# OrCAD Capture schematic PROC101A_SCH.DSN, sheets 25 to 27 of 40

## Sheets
25 35. DEBOUNCE&VOLTAGE-SUPERVISOR: size C; title: DEBOUNCE CIRCUIT & VOLTAGE SUPERVISOR
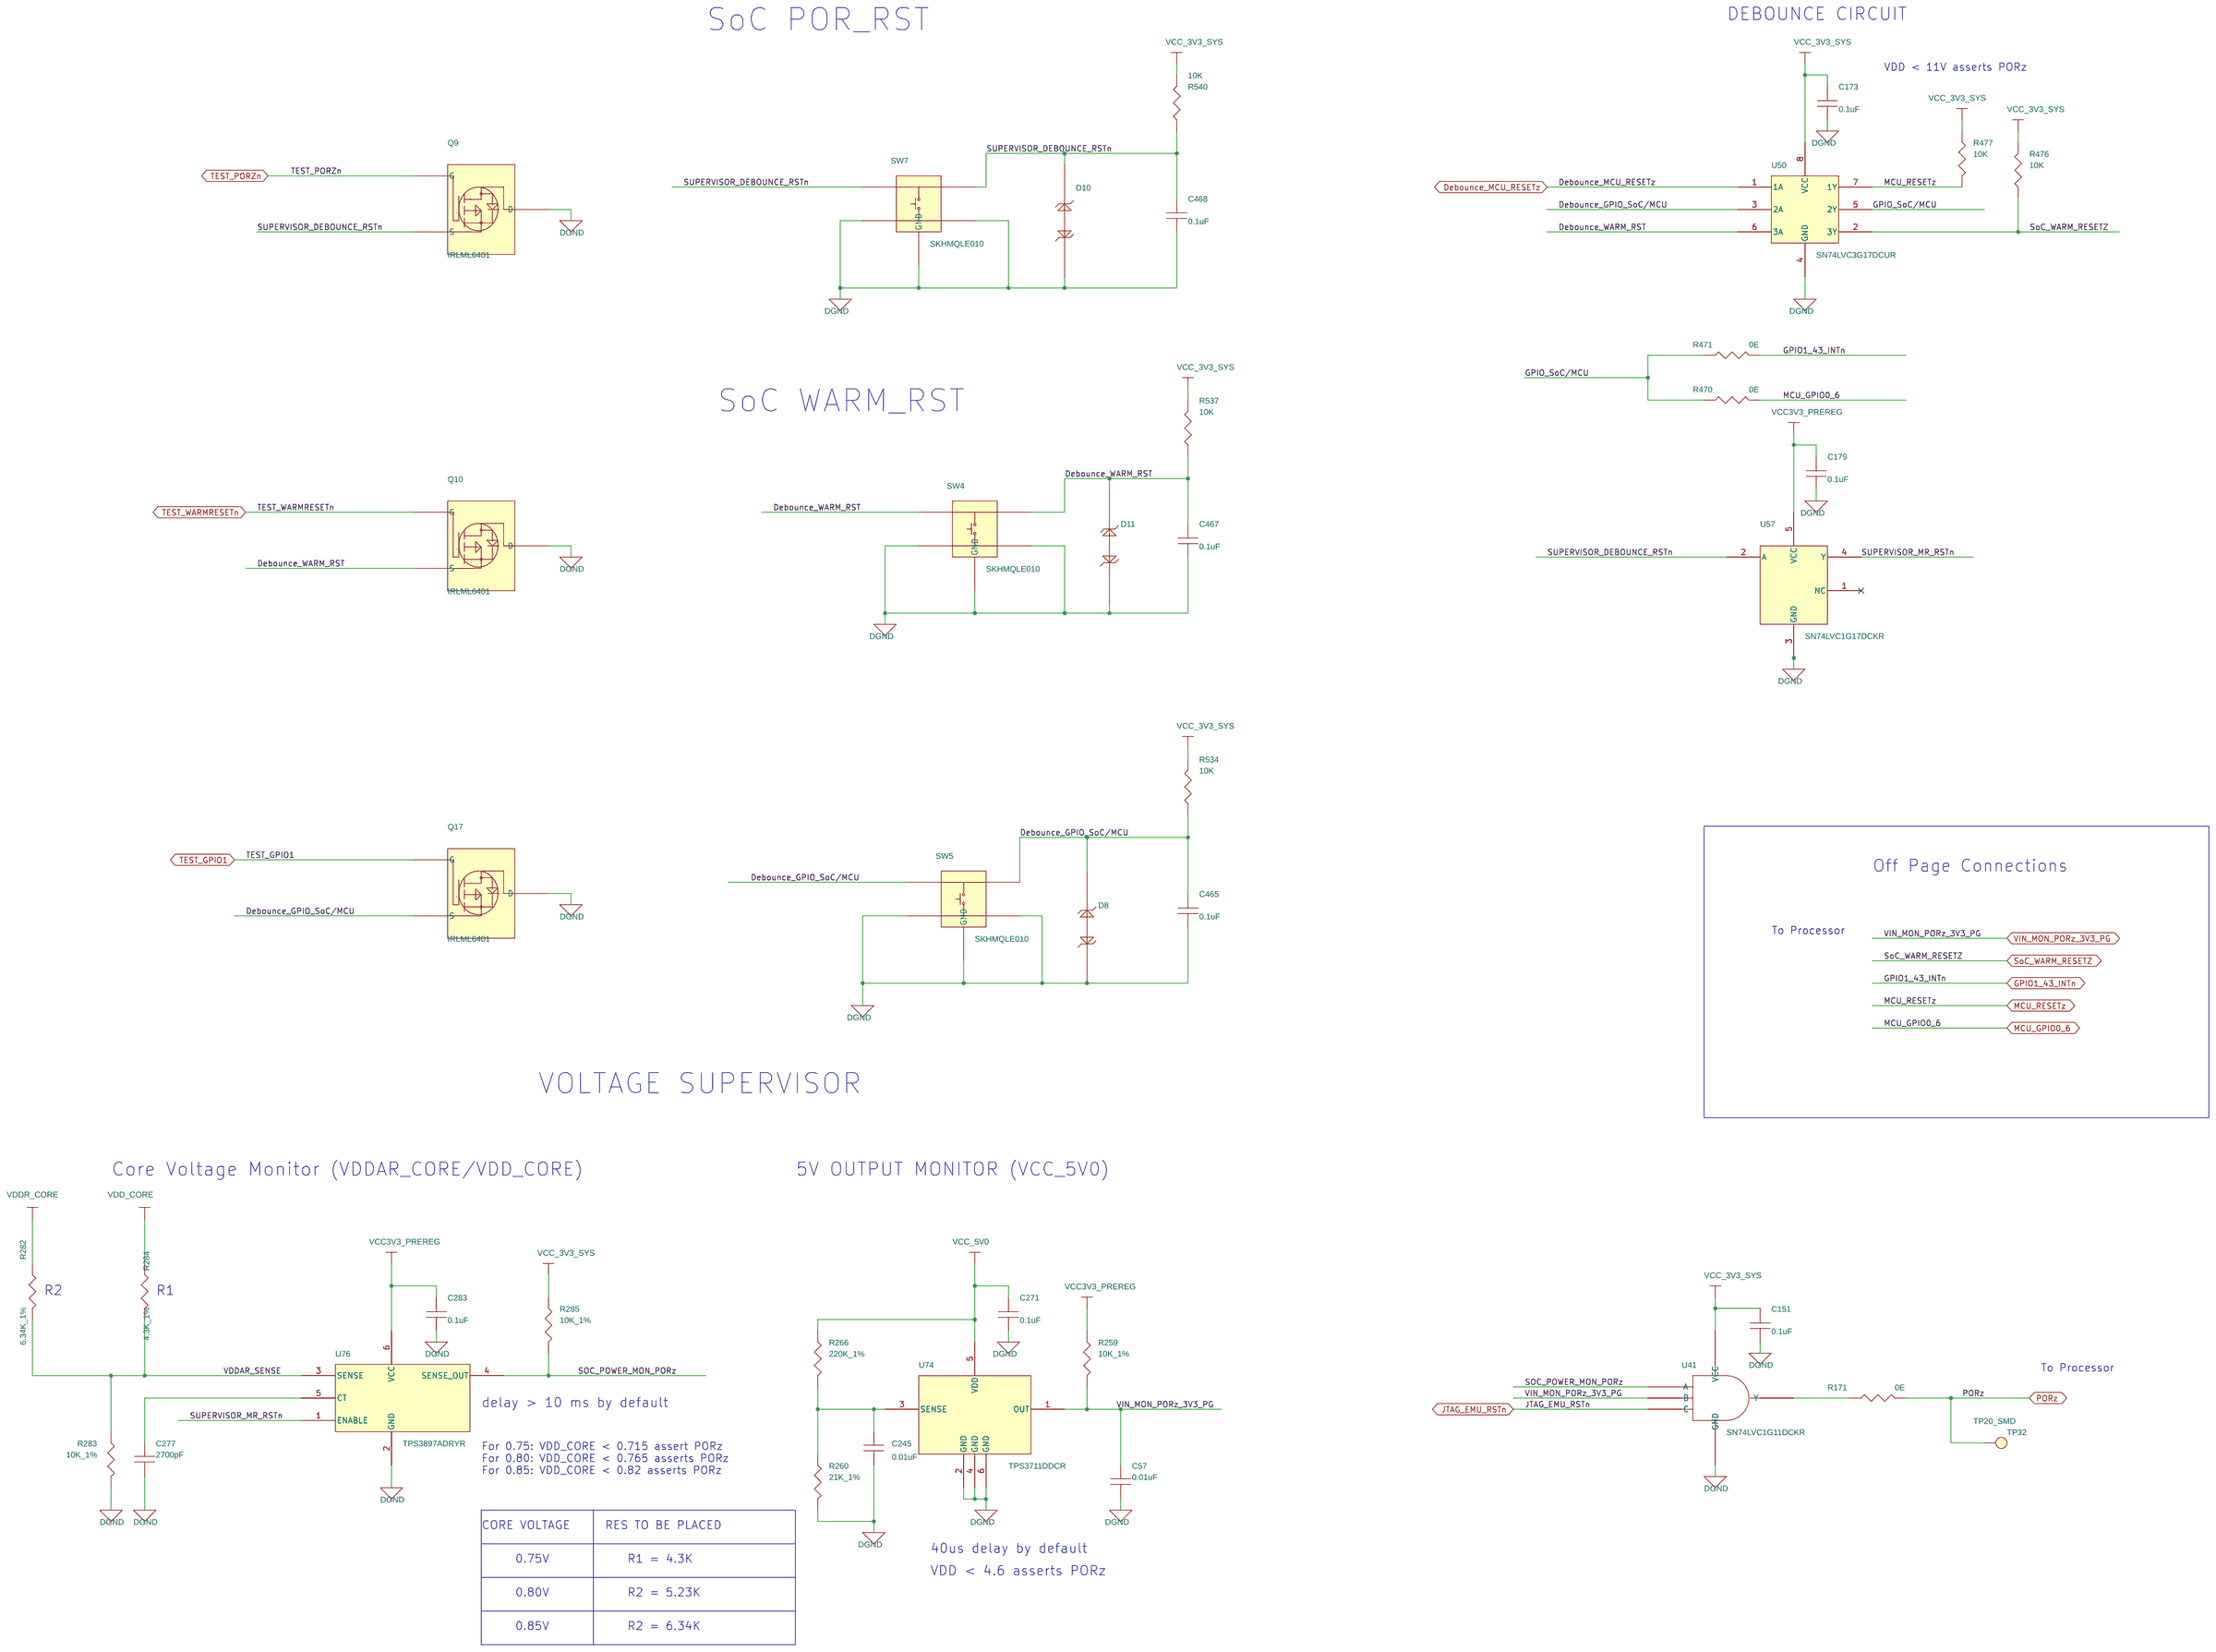
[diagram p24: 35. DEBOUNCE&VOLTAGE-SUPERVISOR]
26 24. MIPI 60 PIN CONNECTOR: size C; title: MIPI 60 PIN CONNECTOR
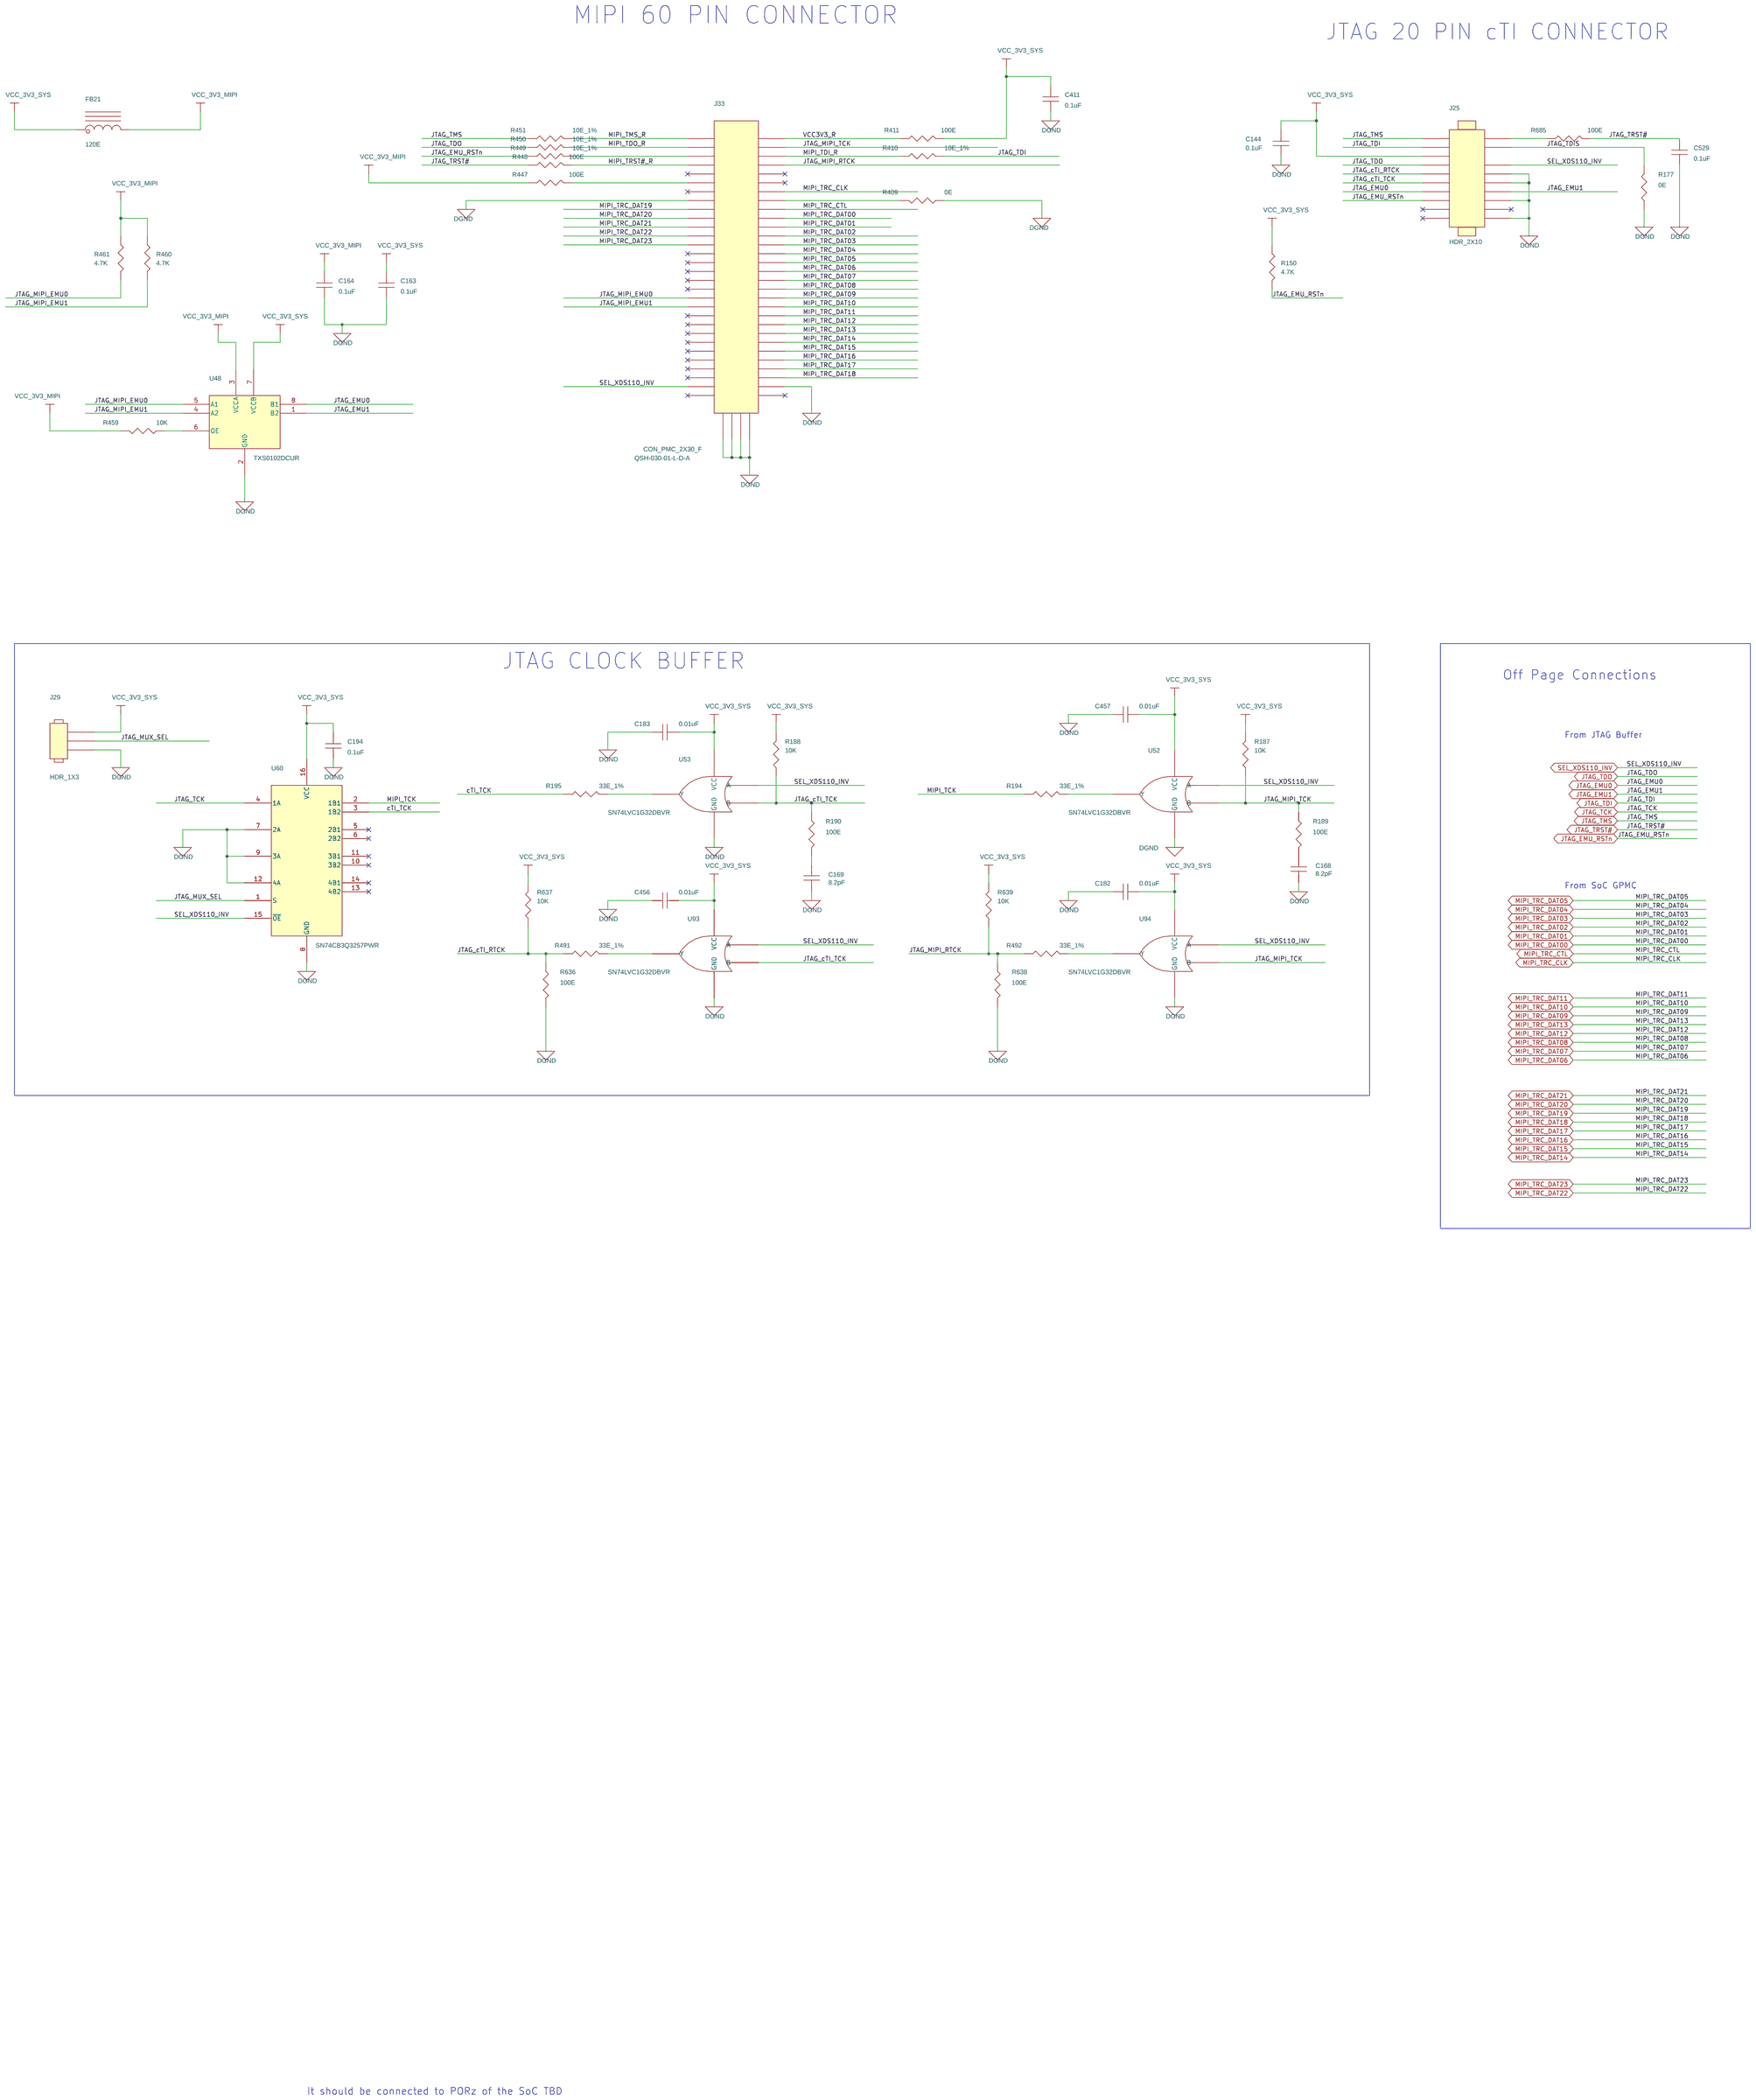
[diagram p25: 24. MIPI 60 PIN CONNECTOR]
27 23. JTAG BUFFER: size C; title: JTAG BUFFER
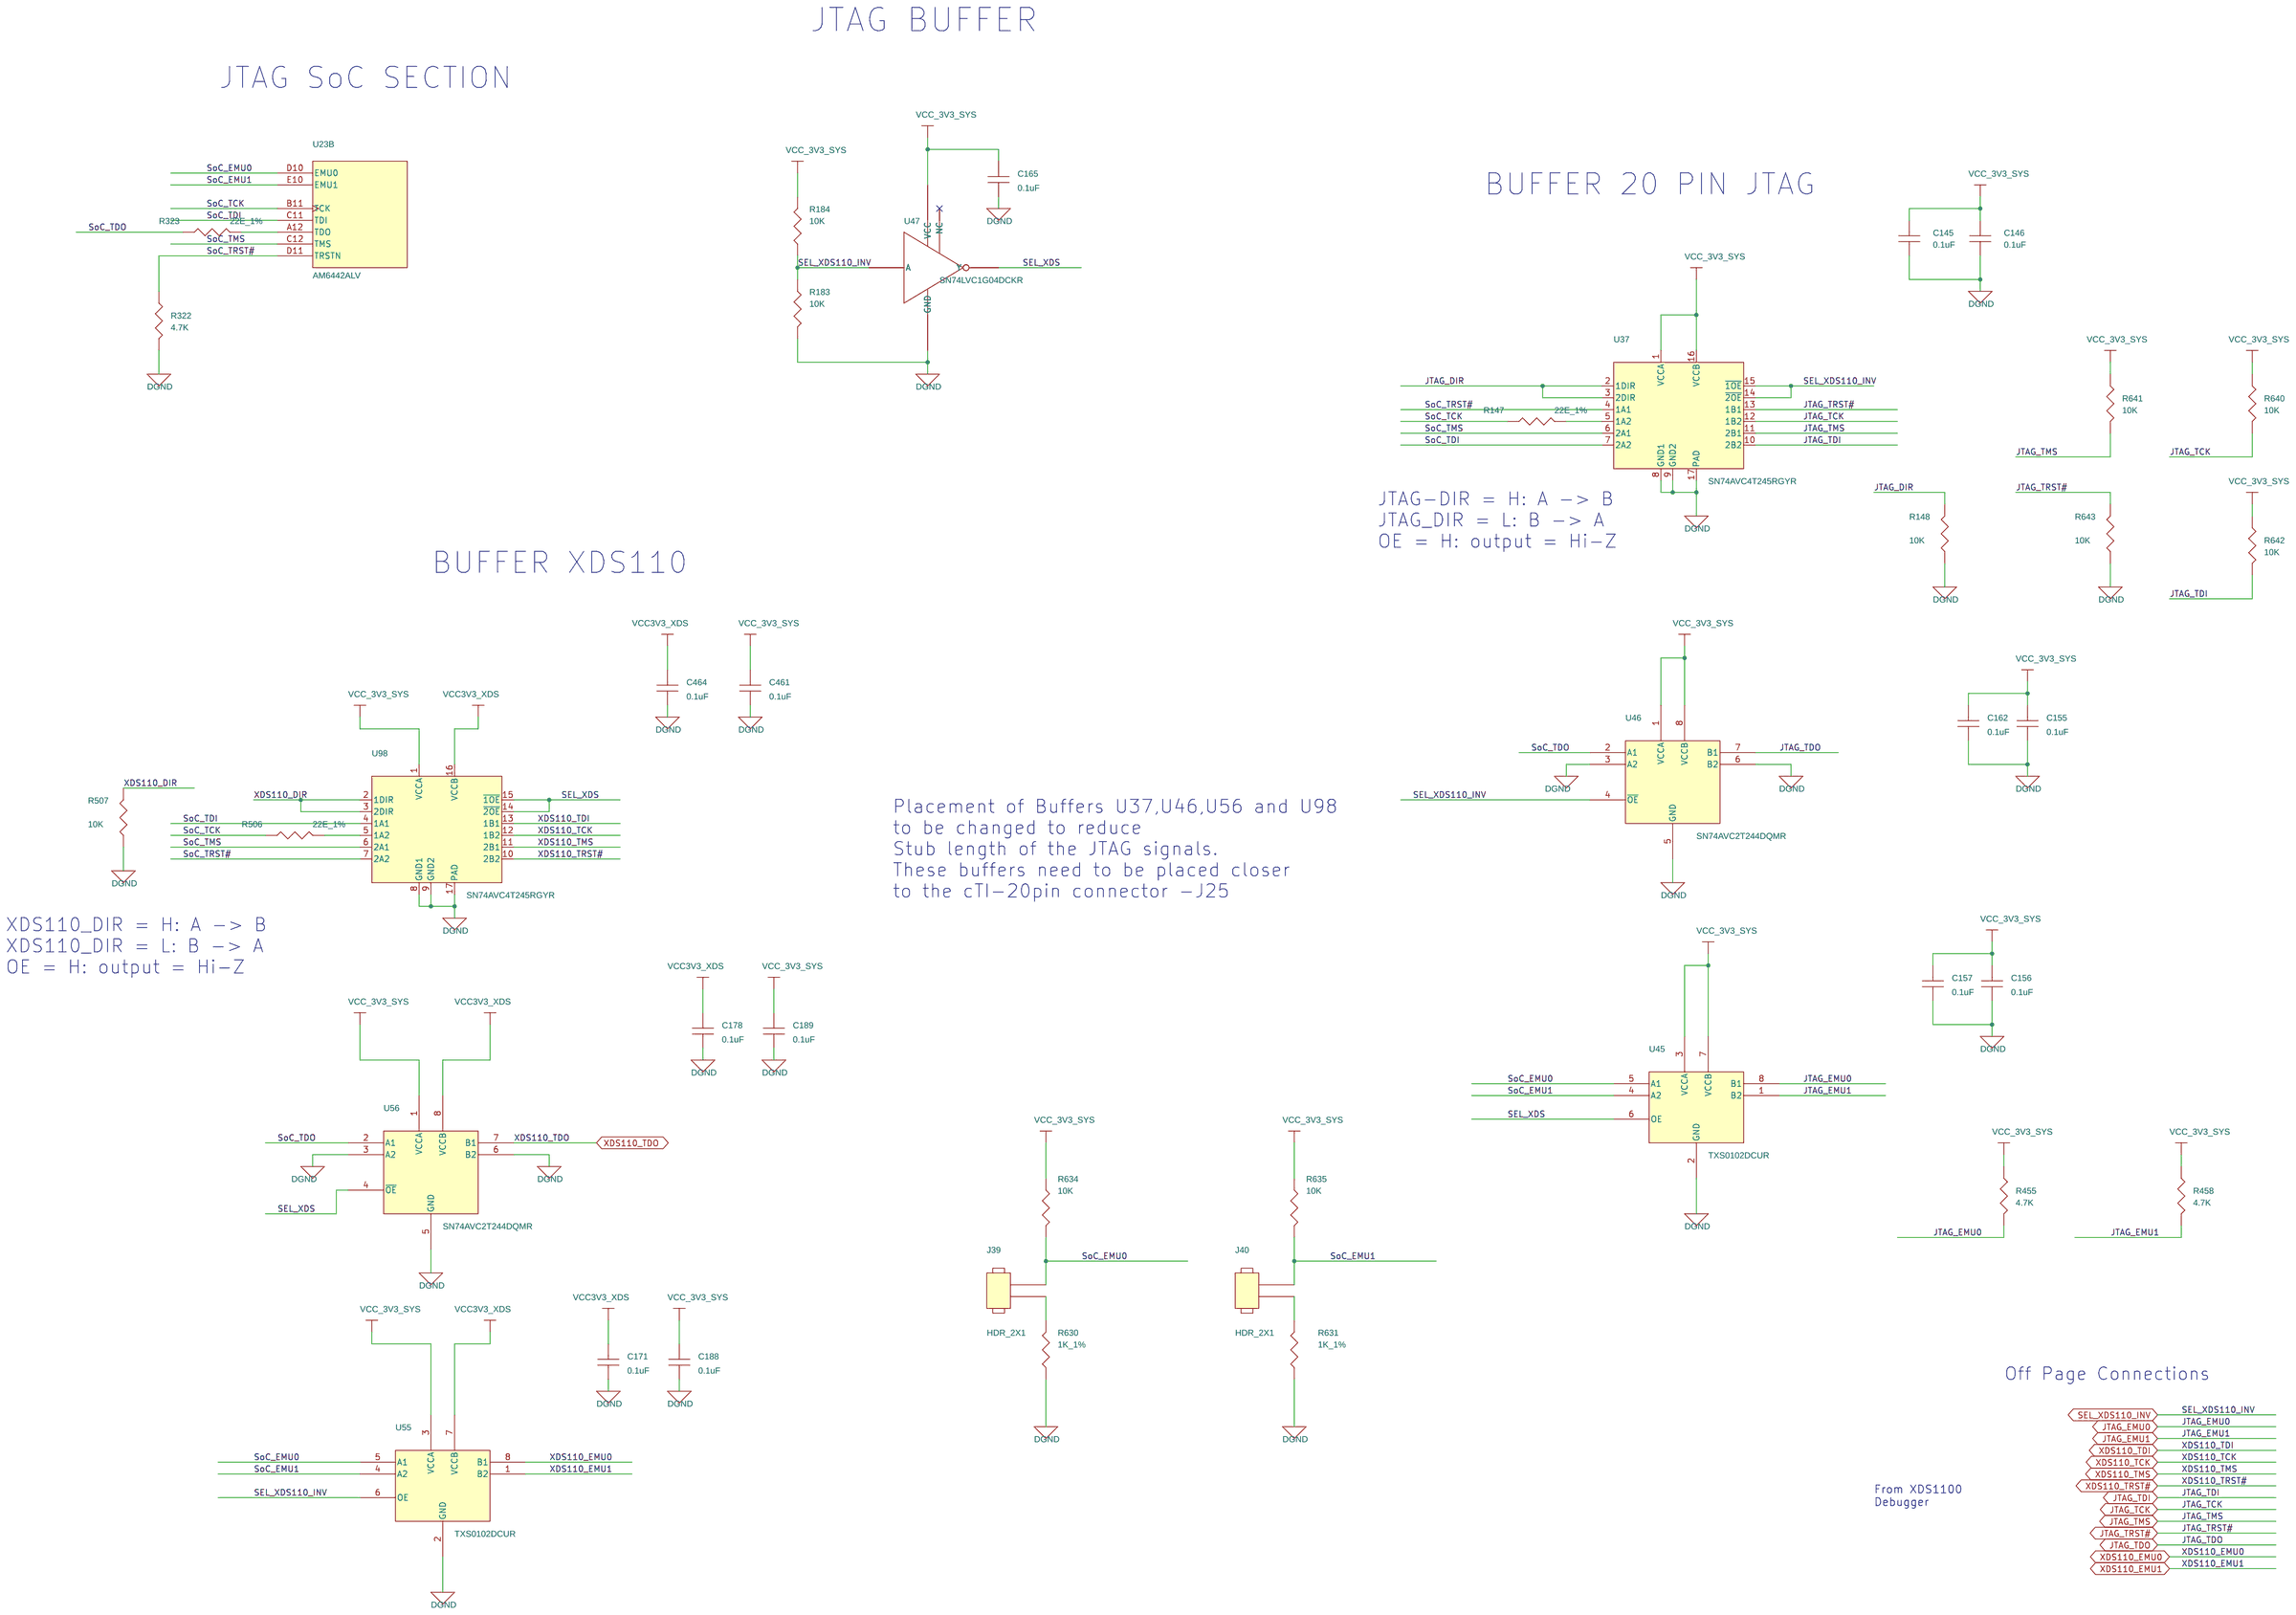
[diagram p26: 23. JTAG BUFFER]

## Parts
sheet 23. JTAG BUFFER
C145  0.1uF  [CAP0402_0-75]
C146  0.1uF  [CAP0402_0-75]
C155  0.1uF  [CAP0402_0-75]
C156  0.1uF  [CAP0402_0-75]
C157  0.1uF  [CAP0402_0-75]
C162  0.1uF  [CAP0402_0-75]
C165  0.1uF  [CAP0402_0-75]
C171  0.1uF  [CAP0402_0-75]
C178  0.1uF  [CAP0402_0-75]
C188  0.1uF  [CAP0402_0-75]
C189  0.1uF  [CAP0402_0-75]
C461  0.1uF  [CAP0402_0-75]
C464  0.1uF  [CAP0402_0-75]
J39  HDR_2X1  [HDR_2X1_100_S_T_10-8]
J40  HDR_2X1  [HDR_2X1_100_S_T_10-8]
R147  22E_1%  [RES0402_0-5]
R148  10K  [RES0402_0-5]
R183  10K  [RES0402_0-5]
R184  10K  [RES0402_0-5]
R322  4.7K  [RES0402_0-5]
R323  22E_1%  [RES0402_0-5]
R455  4.7K  [RES0402_0-5]
R458  4.7K  [RES0402_0-5]
R506  22E_1%  [RES0402_0-5]
R507  10K  [RES0402_0-5]
R630  1K_1%  [RES0402_0-5]
R631  1K_1%  [RES0402_0-5]
R634  10K  [RES0402_0-5]
R635  10K  [RES0402_0-5]
R640  10K  [RES0402_0-5]
R641  10K  [RES0402_0-5]
R642  10K  [RES0402_0-5]
R643  10K  [RES0402_0-5]
U37  SN74AVC4T245RGYR  [QFN16_19-68_160X140]
U45  TXS0102DCUR  [VSSOP8_19-68_85X95_0-9]
U46  SN74AVC2T244DQMR  [X2SON8_15-74_70X50]
U47  SN74LVC1G04DCKR  [SC70-5]
U55  TXS0102DCUR  [VSSOP8_19-68_85X95_0-9]
U56  SN74AVC2T244DQMR  [X2SON8_15-74_70X50]
U98  SN74AVC4T245RGYR  [QFN16_19-68_160X140]
sheet 24. MIPI 60 PIN CONNECTOR
C144  0.1uF  [CAP0402_0-75]
C163  0.1uF  [CAP0402_0-75]
C164  0.1uF  [CAP0402_0-75]
C168  8.2pF  [CAP0402_0-75]
C169  8.2pF  [CAP0402_0-75]
C182  0.01uF  [CAP0402_0-75]
C183  0.01uF  [CAP0402_0-75]
C194  0.1uF  [CAP0402_0-75]
C411  0.1uF  [CAP0402_0-75]
C456  0.01uF  [CAP0402_0-75]
C457  0.01uF  [CAP0402_0-75]
C529  0.1uF  [CAP0402_0-75]
FB21  120E  [IND0603_1]
J25  HDR_2X10  [HDR_2X10_FTR-110-51-D-06_S_S_8-7]
J29  HDR_1X3  [HDR_3X1_100_S_T]
J33  CON_PMC_2X30_F  [CON_PMC2X30_QSH-030-01-D-A_S_S_S_3-3]
R150  4.7K  [RES0402_0-5]
R177  0E  [RES0402_0-5]
R187  10K  [RES0402_0-5]
R188  10K  [RES0402_0-5]
R189  100E  [RES0402_0-5]
R190  100E  [RES0402_0-5]
R194  33E_1%  [RES0402_0-5]
R195  33E_1%  [RES0402_0-5]
R409  0E  [RES0402_0-5]
R410  10E_1%  [RES0402_0-5]
R411  100E  [RES0402_0-5]
R447  100E  [RES0402_0-5]
R448  100E  [RES0402_0-5]
R449  10E_1%  [RES0402_0-5]
R450  10E_1%  [RES0402_0-5]
R451  10E_1%  [RES0402_0-5]
R459  10K  [RES0402_0-5]
R460  4.7K  [RES0402_0-5]
R461  4.7K  [RES0402_0-5]
R491  33E_1%  [RES0402_0-5]
R492  33E_1%  [RES0402_0-5]
R636  100E  [RES0402_0-5]
R637  10K  [RES0402_0-5]
R638  100E  [RES0402_0-5]
R639  10K  [RES0402_0-5]
R685  100E  [RES0402_0-5]
U48  TXS0102DCUR  [VSSOP8_19-68_85X95_0-9]
U52  SN74LVC1G32DBVR  [SOT23-5_1-5]
U53  SN74LVC1G32DBVR  [SOT23-5_1-5]
U60  SN74CB3Q3257PWR  [TSSOP16_25-59_205X180]
U93  SN74LVC1G32DBVR  [SOT23-5_1-5]
U94  SN74LVC1G32DBVR  [SOT23-5_1-5]
sheet 28.GPMC & FSI CONNECTOR
U23  AM6442ALV  [FCBGA441_31-49_680X680_2-6]  (sections A,B,C,D,E,F,G,H,I,J,K,L,M,N,O,P)
sheet 35. DEBOUNCE&VOLTAGE-SUPERVISOR
C57  0.01uF  [CAP0402_0-75]
C151  0.1uF  [CAP0402_0-75]
C173  0.1uF  [CAP0402_0-75]
C179  0.1uF  [CAP0402_0-75]
C245  0.01uF  [CAP0402_0-75]
C271  0.1uF  [CAP0402_0-75]
C277  2700pF  [CAP0603_1]
C283  0.1uF  [CAP0402_0-75]
C465  0.1uF  [CAP0402_0-75]
C467  0.1uF  [CAP0402_0-75]
C468  0.1uF  [CAP0402_0-75]
D8  TPD1E10B06DPYR  [DIO_DFN0402_0-5]
D10  TPD1E10B06DPYR  [DIO_DFN0402_0-5]
D11  TPD1E10B06DPYR  [DIO_DFN0402_0-5]
Q9  IRLML6401  [TO_SOT23-123]
Q10  IRLML6401  [TO_SOT23-123]
Q17  IRLML6401  [TO_SOT23-123]
R171  0E  [RES0402_0-5]
R259  10K_1%  [RES0402_0-5]
R260  21K_1%  [RES0402_0-5]
R266  220K_1%  [RES0402_0-5]
R282  6.34K_1%  [RES0402_0-5]
R283  10K_1%  [RES0402_0-5]
R284  4.3K_1%  [RES0402_0-5]
R285  10K_1%  [RES0402_0-5]
R470  0E  [RES0402_0-5]
R471  0E  [RES0402_0-5]
R476  10K  [RES0402_0-5]
R477  10K  [RES0402_0-5]
R534  10K  [RES0402_0-5]
R537  10K  [RES0402_0-5]
R540  10K  [RES0402_0-5]
SW4  SKHMQLE010  [SW4_SKHMQLE010_240X260_SMD_3-1]
SW5  SKHMQLE010  [SW4_SKHMQLE010_240X260_SMD_3-1]
SW7  SKHMQLE010  [SW4_SKHMQLE010_240X260_SMD_3-1]
TP32  TP20_SMD  [TP20_SMD]
U41  SN74LVC1G11DCKR  [SC70-6]
U50  SN74LVC3G17DCUR  [VSSOP8_19-68_85X95_0-9]
U57  SN74LVC1G17DCKR  [SC70-5]
U74  TPS3711DDCR  [SOT23-6_1-1]
U76  TPS3897ADRYR  [SON6_19-68_40X60_0-6]

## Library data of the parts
C144-C146 C151 C155-C157 C162-C165 C171 C173 C178 C179 C188 C189 C194 C271 C283 C411 C461 C464 C465 C467 C468 C529 = CAP: CAP CERAMIC 0.1uF 25V 20% X5R 0402; Alt_Mfr_name: YAGEO AMERICA; Alt_Mfr_part_number: CC0402KRX5R8BB104; Chkd/date: MANIRAJA/170820; Crtd /date: ALVY/170820; Custom_Duty: 15%; Customs_HS_Code: 85322990; Distributor_name: DIGIKEY; Distributor_part_number: 732-7495-1-ND; Footprint Path: Y:\MIS_DATABASE\Library\ALTIUM_TOOL\PCB_FOOTPRINTS\Altium_Footprint_Lib.PcbLib; Height: 0.55MM; Library Path: Y:\MIS_DATABASE\Library\ALTIUM_TOOL\SCHEMATICS_PARTS\MS_DISCRETE_Library.schlib; Mfr_name: WURTH ELECTRONICS; Mfr_part_number: 885012105018; Mistral Part No: 120020080003-R; Package: 0402; Part_type: CAPACITORS\CERAMIC; Project: AM64x_EVM_BRD; RoHS: RoHS; Temperature: -55°C+85°C; Tolerance: 20%; Voltage: 25V; Wattage: NA; Weight: 0.65mg; Datasheet: Y:\MIS_DATABASE\DATASHEETS\CAPACITORS\885012105018.PDF
J39 J40 = HEADER_2X1: CON HDR 2X1 2.54MM PITCH ST TH; Chkd/date: VASANTHA/060117; Crtd /date: MAZHAR/280405; Custom_Duty: 24%; Customs_HS_Code: 85369090; Distributor_name: DIGIKEY; Distributor_part_number: WM4000-ND; Footprint Path: Y:\MIS_DATABASE\Library\ALTIUM_TOOL\PCB_FOOTPRINTS\Altium_Footprint_Lib.PcbLib; Height: 10.79MM; Library Path: Y:\MIS_DATABASE\Library\ALTIUM_TOOL\SCHEMATICS_PARTS\MS_Connector_Library.schlib; Mfr_name: MOLEX; Mfr_part_number: 22-03-2021; Mistral Part No: 150009030246-R; Package: THRU-HOLE; Part_type: CONNECTOR\HEADERS; Project: FPGA EXTENDER CARD; RoHS: RoHS; Temperature: -0°C+75°C; Tolerance: NA; Voltage: NA; Wattage: NA; Weight: 139gm; Datasheet: Y:\MIS_DATABASE\DATASHEETS\CONNECTORS\HEADER_X4030.PDF
R147 R323 R506 = RESISTOR: RES 22E 1/16W 1% 0402; Chkd/date: SUHAS/290910; Crtd /date: MAZHAR/090909; Cust_part_number: 4700-80047E; Custom_Duty: 15%; Customs_HS_Code: 85332119; Distributor_name: DIGIKEY; Distributor_part_number: 311-22.0LRCT-ND; Footprint Path: Y:\MIS_DATABASE\Library\ALTIUM_TOOL\PCB_FOOTPRINTS\Altium_Footprint_Lib.PcbLib; Height: 0.40MM; Library Path: Y:\MIS_DATABASE\Library\ALTIUM_TOOL\SCHEMATICS_PARTS\MS_DISCRETE_Library.schlib; Mfr_name: YAGEO AMERICA; Mfr_part_number: RC0402FR-0722RL; Mistral Part No: 110009090004-R; Package: 0402; Part_type: RESISTORS\FIXED; Project: VMEFMCD; RoHS: RoHS; SIGNAL_MODEL: RESISTOR_RES0402_22E_22E; Temperature: -55°C+155°C; Tolerance: 1%; Voltage: NA; Wattage: 1/16W; Weight: 0.65mg; Datasheet: Y:\MIS_DATABASE\DATASHEETS\RESISTORS\RCXXXXL-SER_MAR18.PDF
R148 R183 R184 R187 R188 R459 R476 R477 R507 R534 R537 R540 R634 R635 R637 R639-R643 = RESISTOR: RES 10K 1/16W 5% 0402; Chkd/date: VASANTHA/061216; Crtd /date: MAZHAR/230805; Custom_Duty: 15%; Customs_HS_Code: 85332119; Distributor_name: DIGIKEY; Distributor_part_number: 311-10KJRCT-ND; Footprint Path: Y:\MIS_DATABASE\Library\ALTIUM_TOOL\PCB_FOOTPRINTS\Altium_Footprint_Lib.PcbLib; Height: 0.40MM; Library Path: Y:\MIS_DATABASE\Library\ALTIUM_TOOL\SCHEMATICS_PARTS\MS_DISCRETE_Library.schlib; Mfr_name: YAGEO AMERICA; Mfr_part_number: RC0402JR-0710KL; Mistral Part No: 110011060021-R; Package: 0402; Part_type: RESISTORS\FIXED; Project: HSE; RoHS: RoHS; Temperature: -55°C+155°C; Tolerance: 5%; Voltage: NA; Wattage: 1/16W; Weight: 0.65mg; Datasheet: Y:\MIS_DATABASE\DATASHEETS\RESISTORS\RCXXXXL-SER_MAR18.PDF
R150 R322 R455 R458 R460 R461 = RESISTOR: RES 4.7K 1/16W 5% 0402; Chkd/date: VASANTHA/130516; Crtd /date: VASANTHA/130516; Custom_Duty: 15%; Customs_HS_Code: 85332119; Distributor_name: DIGIKEY; Distributor_part_number: 311-4.7KJRCT-ND; Footprint Path: Y:\MIS_DATABASE\Library\ALTIUM_TOOL\PCB_FOOTPRINTS\Altium_Footprint_Lib.PcbLib; Height: 0.40MM; Library Path: Y:\MIS_DATABASE\Library\ALTIUM_TOOL\SCHEMATICS_PARTS\MS_DISCRETE_Library.schlib; Mfr_name: YAGEO AMERICA; Mfr_part_number: RC0402JR-074K7L; Mistral Part No: 110011060001-R; Package: 0402; Part_type: RESISTORS\FIXED; Project: TMDXCSK368; RoHS: RoHS; Temperature: -55°C+155°C; Tolerance: 5%; Voltage: NA; Wattage: 1/16W; Weight: 0.65mg; Datasheet: Y:\MIS_DATABASE\DATASHEETS\RESISTORS\RCXXXXL-SER_MAR18.PDF
R630 R631 = RESISTOR: RES 1K 1/10W 1% 0402; Chkd/date: VASANTHA/281216; Crtd /date: MAZHAR/150506; Custom_Duty: 15%; Customs_HS_Code: 85332119; Distributor_name: DIGIKEY; Distributor_part_number: P1.00KLCT-ND; Footprint Path: Y:\MIS_DATABASE\Library\ALTIUM_TOOL\PCB_FOOTPRINTS\Altium_Footprint_Lib.PcbLib; Height: 0.40MM; Library Path: Y:\MIS_DATABASE\Library\ALTIUM_TOOL\SCHEMATICS_PARTS\MS_DISCRETE_Library.schlib; Mfr_name: PANASONIC-ECG; Mfr_part_number: ERJ-2RKF1001X; Mistral Part No: 110009030411-R; Package: 0402; Part_type: RESISTORS\FIXED; Project: VOCERA; RoHS: RoHS; Temperature: -55°C+155°C; Tolerance: 1%; Voltage: NA; Wattage: 1/10W; Weight: 0.8mg; Datasheet: Y:\MIS_DATABASE\DATASHEETS\RESISTORS\PAN-ERJSER_NOV17.PDF
U37 U98 = SN74AVC4T245RGYR_QFN16: IC 4-BIT DUAL SUPPLY BUS TRANSCEIVER QFN16; Chkd/date: MAZHAR/060308; Crtd /date: USMAN/060308; Custom_Duty: 15%; Customs_HS_Code: 85423100; Distributor_name: DIGIKEY; Distributor_part_number: 296-18231-1-ND; Height: 1.00MM; Mfr_name: TEXAS INSTRUMENTS; Mistral Part No: 141009030112-R; Package: QFN16; Part_type: ICS\DIGITAL\COMBINATIONAL; Project: HS100RD; RoHS: Sb/ Br FREE; Datasheet: Y:\MIS_DATABASE\DATASHEETS\ICS\DIGITAL\BUSTRANSCEIVER\SN74AVC4T245XXXX.PDF
U45 U48 U55 = TXS0102DCUR_VSSOP8: IC 2BIT BI-DIR VOLTAGE-LEVEL TRANSLATOR US8(VSSOP8); Chkd/date: MANIRAJA/130617; Crtd /date: SHREESHAIL/190108; Custom_Duty: 15%; Customs_HS_Code: 85423100; Distributor_name: DIGIKEY; Distributor_part_number: 296-21931-1-ND; Footprint Path: Y:\MIS_DATABASE\Library\ALTIUM_TOOL\PCB_FOOTPRINTS\Altium_Footprint_Lib.PcbLib; Height: 0.90MM; Library Path: Y:\MIS_DATABASE\Library\ALTIUM_TOOL\SCHEMATICS_PARTS\MS_MISCINTERFACE_Library.schlib; Mfr_name: TEXAS INSTRUMENTS; Mistral Part No: 141009030376-R; Package: US8; Part_type: ICS\INTERFACE\LEVEL TRANSLATOR; Project: SD_WATERLOO; RoHS: RoHS; Temperature: -40°C+85°C; Tolerance: NA; Voltage: NA; Wattage: NA; Weight: 9.6mg; Datasheet: Y:\MIS_DATABASE\DATASHEETS\ICS\INTERFACE\TXS0102.PDF
U46 U56 = SN74AVC2T244DQMR_X2SON8: IC 2-BIT UNDIRECTIONAL VOLTAGE-LEVEL TRANSLATOR X2SON8; Chkd/date: VASANTHA/060516; Crtd /date: VASANTHA/030316; Customs_HS_Code: 15%; Distributor_name: DIGIKEY; Distributor_part_number: 296-29674-1-ND; Height: 0.40MM; Mfr_name: TEXAS INSTRUMENTS; Mistral Part No: 141016030002-R; Package: X2SON8; Part_type: ICS\INTERFACE\LEVEL TRANSLATOR; Pb-Free: 85423100; Project: OCTASIC_3600; RoHS: RoHS; Temperature: -40°C+85°C; Tolerance: NA; Voltage: NA; Wattage: NA; Weight: NA; Datasheet: Y:\MIS_DATABASE\DATASHEETS\ICS\INTERFACE\SN74AVC2T244.PDF
U47 = SN74LVC1G04DCKR_SC70-5: IC SINGLE INVERTER GATE SC70-5; Chkd/date: SUHAS/221010; Crtd /date: USMAN/150709; Custom_Duty: 15%; Customs_HS_Code: 85423100; Distributor_name: DIGIKEY; Distributor_part_number: 296-11600-1-ND; Height: 1.10MM; Mfr_name: TEXAS INSTRUMENTS; Mistral Part No: 141009070007-R; Part_type: ICS\DIGITAL\GATES; Project: BUG_BASE-II; RoHS: Sb/ Br FREE; Temperature: -40°C+85°C; Datasheet: Y:\MIS_DATABASE\DATASHEETS\ICS\DIGITAL\GATES\SN74LVC1G04-1.PDF
C168 C169 = CAP: CAP CERAMIC 8.2pF 100V 0.5pF C0G(NP0) 0402; Chkd/date: MANIRAJA/170820; Crtd /date: ALVY/170820; Custom_Duty: 15%; Customs_HS_Code: 85322990; Distributor_name: DIGIKEY; Distributor_part_number: 732-12053-1-ND; Footprint Path: Y:\MIS_DATABASE\Library\ALTIUM_TOOL\PCB_FOOTPRINTS\Altium_Footprint_Lib.PcbLib; Height: 0.55MM; Library Path: Y:\MIS_DATABASE\Library\ALTIUM_TOOL\SCHEMATICS_PARTS\MS_DISCRETE_Library.schlib; Mfr_name: WURTH ELECTRONICS; Mfr_part_number: 885012005085; Mistral Part No: 120020080006-R; Package: 0402; Part_type: CAPACITORS\CERAMIC; Project: AM64x_EVM_BRD; RoHS: RoHS; Temperature: -55°C+125°C; Tolerance: 0.5pF%; Voltage: 100V; Wattage: NA; Weight: 2.261mg; Datasheet: Y:\MIS_DATABASE\DATASHEETS\CAPACITORS\885012005085.PDF
C57 C182 C183 C245 C456 C457 = CAP: CAP CERAMIC 0.01uF 25V 10% X7R 0402; Chkd/date: MANIRAJA/170820; Crtd /date: ALVY/170820; Custom_Duty: 15%; Customs_HS_Code: 85322990; Distributor_name: DIGIKEY; Distributor_part_number: 732-7545-1-ND; Footprint Path: Y:\MIS_DATABASE\Library\ALTIUM_TOOL\PCB_FOOTPRINTS\Altium_Footprint_Lib.PcbLib; Height: 0.55MM; Library Path: Y:\MIS_DATABASE\Library\ALTIUM_TOOL\SCHEMATICS_PARTS\MS_DISCRETE_Library.schlib; Mfr_name: WURTH ELECTRONICS; Mfr_part_number: 885012205050; Mistral Part No: 120011090040-R; Package: 0402; Part_type: CAPACITORS\CERAMIC; Project: AM64x_EVM_BRD; RoHS: RoHS; Temperature: -55°C+125°C; Tolerance: 10%; Voltage: 25V; Wattage: NA; Weight: 0.65mg; Datasheet: Y:\MIS_DATABASE\DATASHEETS\CAPACITORS\885012205050.PDF
FB21 = INDUCTOR_FERRITE: IND FERRITE BEAD CHIP 120E 2A 0603; Chkd/date: MANIRAJA/180820; Crtd /date: ALVY/180820; Custom_Duty: 24%; Customs_HS_Code: 85437099; Distributor_name: DIGIKEY; Distributor_part_number: 732-782631141CT-ND; Footprint Path: Y:\MIS_DATABASE\Library\ALTIUM_TOOL\PCB_FOOTPRINTS\Altium_Footprint_Lib.PcbLib; Height: 1.00MM; Library Path: Y:\MIS_DATABASE\Library\ALTIUM_TOOL\SCHEMATICS_PARTS\MS_FILTER_Library.schlib; Mfr_name: WURTH ELECTRONICS; Mfr_part_number: 782631141; Mistral Part No: 130020080015-R; Package: 0603; Part_type: INDUCTOR; Project: AM64x_EVM_BRD; RoHS: RoHS; Temperature: -55°C+125°C; Tolerance: 25%; Voltage: NA; Wattage: NA; Weight: NA; Datasheet: Y:\MIS_DATABASE\DATASHEETS\DISCRETES\INDUCTORS\782631141.PDF
J25 = HEADER_10X2_FTR-06: CON HDR 2X10 1.27MM PITCH ST SMD; Chkd/date: MANIRAJA/031218; Crtd /date: CHAITHANYA/050811; Custom_Duty: 24%; Customs_HS_Code: 85369090; Distributor_name: DIGIKEY; Distributor_part_number: SAM8792-ND; Footprint Path: Y:\MIS_DATABASE\Library\ALTIUM_TOOL\PCB_FOOTPRINTS\Altium_Footprint_Lib.PcbLib; Height: 8.67MM; Library Path: Y:\MIS_DATABASE\Library\ALTIUM_TOOL\SCHEMATICS_PARTS\MS_CONNECTOR_Library.schlib; Mfr_name: SAMTEC; Mfr_part_number: FTR-110-51-S-D-06; Mistral Part No: 150011090001-R; Package: SMD; Part_type: CONNECTOR\HEADERS; Project: GEMYC; RoHS: RoHS; Temperature: -55°C+125°C; Tolerance: NA; Voltage: NA; Wattage: NA; Weight: NA; Datasheet: Y:\MIS_DATABASE\DATASHEETS\CONNECTORS\FTR-D-SER.PDF
J29 = HEADER_3X1: HDR 1X3 2.54MM PITCH ST TH; Chkd/date: VASANTHA/290616; Crtd /date: VASANTHA/290616; Custom_Duty: 15%; Customs_HS_Code: 85322990; Distributor_name: DIGIKEY; Distributor_part_number: 609-3471-ND; Height: 8.58MM; Mfr_name: FCI; Mfr_part_number: 68001-403HLF; Mistral Part No: 150016060025-R; Package: THRU-HOLE; Part_type: CONNECTOR\HEADERS; Project: IKEYP; RoHS: RoHS; Temperature: -40°C+105°C; Tolerance: NA; Voltage: NA; Wattage: NA; Weight: NA; Datasheet: Y:\MIS_DATABASE\DATASHEETS\CONNECTORS\68000.PDF
J33 = CON_PMC_30X2_F: CON PMC 2X30 0.50MM PITCH FEMALE ST SMD; Chkd/date: MANIRAJA/011018; Crtd /date: USMAN/051108; Custom_Duty: 24%; Customs_HS_Code: 85369090; Distributor_name: DIGIKEY; Distributor_part_number: SAM8180-ND; Footprint Path: Y:\MIS_DATABASE\Library\ALTIUM_TOOL\PCB_FOOTPRINTS\Altium_Footprint_Lib.PcbLib; Height: 3.25MM; Library Path: Y:\MIS_DATABASE\Library\ALTIUM_TOOL\SCHEMATICS_PARTS\MS_CONNECTOR_Library.schlib; Library Ref: CON_PMC_30X2_F_4SH; Mfr_name: SAMTEC; Mfr_part_number: QSH-030-01-L-D-A; Mistral Part No: 150009030606-R; Package: SMD; Part_type: CONNECTOR\PMC; Project: KHAN_HSST; RoHS: RoHS; Temperature: -55°C+125°C; Tolerance: NA; Voltage: NA; Wattage: NA; Weight: NA; Datasheet: Y:\MIS_DATABASE\DATASHEETS\CONNECTORS\QSH.PDF
R171 R177 R409 R470 R471 = RESISTOR: RES 0E 1/16W JUMPER 0402; Chkd/date: VASANTHA/201216; Crtd /date: MUDDU/190810; Custom_Duty: 15%; Customs_HS_Code: 85332119; Distributor_name: DIGIKEY; Distributor_part_number: 541-0.0JCT-ND; Footprint Path: Y:\MIS_DATABASE\Library\ALTIUM_TOOL\PCB_FOOTPRINTS\Altium_Footprint_Lib.PcbLib; Height: 0.40MM; Library Path: Y:\MIS_DATABASE\Library\ALTIUM_TOOL\SCHEMATICS_PARTS\MS_DISCRETE_Library.schlib; Mfr_name: VISHAY; Mfr_part_number: CRCW04020000Z0ED; Mistral Part No: 110010080019-R; Package: 0402; Part_type: RESISTORS\FIXED; Project: PB_BUGBASE; RoHS: RoHS; Temperature: -55°C+155°C; Tolerance: NA; Voltage: NA; Wattage: 1/16W; Weight: 0.65mg; Datasheet: Y:\MIS_DATABASE\DATASHEETS\RESISTORS\CRCW0603.PDF
R189 R190 R411 R447 R448 R636 R638 R685 = RESISTOR: RES 100E 1/16W 5% 0402; Chkd/date: MANIRAJA/230817; Crtd /date: MANIRAJA/230817; Custom_Duty: 15%; Customs_HS_Code: 85332119; Distributor_name: DIGIKEY; Distributor_part_number: 541-100JCT-ND; Footprint Path: Y:\MIS_DATABASE\Library\ALTIUM_TOOL\PCB_FOOTPRINTS\Altium_Footprint_Lib.PcbLib; Height: 0.40MM; Library Path: Y:\MIS_DATABASE\Library\ALTIUM_TOOL\SCHEMATICS_PARTS\MS_DISCRETE_Library.schlib; Mfr_name: VISHAY; Mfr_part_number: CRCW0402100RJNED; Mistral Part No: 110014060039-R; Package: 0402; Part_type: RESISTORS\FIXED; Project: TI_MAXIE_CPB; RoHS: RoHS; Temperature: -55°C+155°C; Tolerance: 5%; Voltage: NA; Wattage: 1/16W; Weight: 0.65mg; Datasheet: Y:\MIS_DATABASE\DATASHEETS\RESISTORS\CRCW0603.PDF
R194 R195 R491 R492 = RESISTOR: RES 33E 1/10W 1% 0402; Chkd/date: VASANTHA/061216; Crtd /date: JEBRAN/171114; Custom_Duty: 15%; Customs_HS_Code: 85332119; Distributor_name: DIGIKEY; Distributor_part_number: P33.0LCT-ND; Footprint Path: Y:\MIS_DATABASE\Library\ALTIUM_TOOL\PCB_FOOTPRINTS\Altium_Footprint_Lib.PcbLib; Height: 0.40MM; Library Path: Y:\MIS_DATABASE\Library\ALTIUM_TOOL\SCHEMATICS_PARTS\MS_DISCRETE_Library.schlib; Mfr_name: PANASONIC-ECG; Mfr_part_number: ERJ-2RKF33R0X; Mistral Part No: 110014110006-R; Package: 0402; Part_type: RESISTORS\FIXED; Project: ZK BIOMETRIC; RoHS: RoHS; Temperature: -55°C+155°C; Tolerance: 1%; Voltage: NA; Wattage: 1/10W; Weight: 0.8mg; Datasheet: Y:\MIS_DATABASE\DATASHEETS\RESISTORS\PAN-ERJSER_NOV17.PDF
R410 R449-R451 = RESISTOR: RES 10E 1/16W 1% 0402; Chkd/date: MANIRAJA/070218; Crtd /date: ALVY/070218; Custom_Duty: 15%; Customs_HS_Code: 85332119; Distributor_name: DIGIKEY; Distributor_part_number: 311-10.0LRCT-ND; Footprint Path: Y:\MIS_DATABASE\Library\ALTIUM_TOOL\PCB_FOOTPRINTS\Altium_Footprint_Lib.PcbLib; Height: 0.40MM; Library Path: Y:\MIS_DATABASE\Library\ALTIUM_TOOL\SCHEMATICS_PARTS\MS_DISCRETE_Library.schlib; Mfr_name: YAGEO AMERICA; Mfr_part_number: RC0402FR-0710RL; Mistral Part No: 110018020004-R; Package: 0402; Part_type: RESISTORS\FIXED; Project: TI_MAXIE_CPB; RoHS: RoHS; Temperature: -55°C+155°C; Tolerance: 1%; Voltage: NA; Wattage: 1/16W; Weight: 0.65mg; Datasheet: Y:\MIS_DATABASE\DATASHEETS\RESISTORS\RCXXXXL-SER_MAR18.PDF
U52 U53 U93 U94 = SN74LVC1G32DBVR_SOT23-5: IC SINGAL 2 INPUT POSITIVE OR GATE SOT23-5; Chkd/date: MANIRAJA/051017; Crtd /date: MAZHAR/070806; Custom_Duty: 15%; Customs_HS_Code: 85423100; Distributor_name: DIGIKEY; Distributor_part_number: 296-9847-1-ND; Height: 1.45MM; Mfr_name: TEXAS INSTRUMENTS; Mistral Part No: 141009030236-R; Package: SOT23-5; Part_type: ICS\DIGITAL\GATES; Project: SVDO_RMB_MMA; RoHS: RoHS; Temperature: -40°C+85°C; Tolerance: NA; Voltage: NA; Wattage: NA; Weight: 6.3mg; Datasheet: Y:\MIS_DATABASE\DATASHEETS\ICS\DIGITAL\GATES\SN74LVC1G32.PDF
U60 = SN74CB3Q3257PWR_TSSOP16: IC 4BIT 1-OF-2 FET MULTIPLEXER/DEMULTIPLEXER TSSOP16; Chkd/date: SUHAS/251010; Crtd /date: USMAN/060109; Custom_Duty: 15%; Customs_HS_Code: 85423100; Distributor_name: DIGIKEY; Distributor_part_number: 296-19138-1-ND; Height: 1.20MM; Mfr_name: TEXAS INSTRUMENTS; Mistral Part No: 141009030117-R; Package: TSSOP16; Part_type: ICS\DIGITAL\COMBINATIONAL; Project: OMAP_EVM; RoHS: Sb/ Br FREE; Temperature: -40°C+85°C; Datasheet: Y:\MIS_DATABASE\DATASHEETS\ICS\DIGITAL\COMBINATIONAL\SN74CB3Q3257.PDF
U23 = AM64-SVB_BGA441: IC AM64 SoC MICROPROCESSOR BGA441; Chkd/date: MANIRAJA/020520; Crtd /date: ALVY/090420; Custom_Duty: 15%; Customs_HS_Code: 85423100; Distributor_name: NA; Distributor_part_number: NA; Footprint Path: Y:\MIS_DATABASE\Library\ALTIUM_TOOL\PCB_FOOTPRINTS\Altium_Footprint_Lib.PcbLib; Height: 2.57MM; Library Path: Y:\MIS_DATABASE\Library\ALTIUM_TOOL\SCHEMATICS_PARTS\MS_MICROPROCESSOR_Library.schlib; Mfr_name: TEXAS INSTRUMENTS; Mfr_part_number: AM6442ASFGGAALV; Mistral Part No: 141220040002; Package: BGA441; Part_type: ICS\DIGITAL\MICROPROCESSOR; Project: AM64x_SVB BRD; RoHS: NA; Temperature: NA; Tolerance: NA; Voltage: NA; Wattage: NA; Weight: NA; Datasheet: Y:\MIS_DATABASE\DATASHEETS\ICS\DIGITAL\MICROCONTROLLER\AM64-SoC_SVB.PDF
C277 = CAP: CAP CERAMIC 2700pF 50V 5% C0G(NP0) 0603; Chkd/date: BAVISH/050911; Crtd /date: CHAITHANYA/290811; Custom_Duty: 15%; Customs_HS_Code: 85322990; Distributor_name: DIGIKEY; Distributor_part_number: 490-3283-1-ND; Footprint Path: Y:\MIS_DATABASE\Library\ALTIUM_TOOL\PCB_FOOTPRINTS\Altium_Footprint_Lib.PcbLib; Height: 0.90MM; Library Path: Y:\MIS_DATABASE\Library\ALTIUM_TOOL\SCHEMATICS_PARTS\MS_DISCRETE_Library.schlib; Mfr_name: MURATA; Mfr_part_number: GRM1885C1H272JA01D; Mistral Part No: 120011090002-R; Package: 0603; Part_type: CAPACITORS\CERAMIC; Project: GEMYC; RoHS: RoHS; Temperature: -55°C+125°C; Tolerance: 5%; Voltage: 50V; Wattage: NA; Weight: 6.3mg; Datasheet: Y:\MIS_DATABASE\DATASHEETS\CAPACITORS\MURATA-GXX-SER_NOV17.PDF
D8 D10 D11 = DIODE_SOD323: DIODE 1CH ESD PROTECTION X1SON2; Chkd/date: MANIRAJA/040420; Crtd /date: VASANTHA/181114; Custom_Duty: 15%; Customs_HS_Code: 85423100; Distributor_name: DIGIKEY; Distributor_part_number: 296-30406-1-ND; Footprint Path: Y:\MIS_DATABASE\Library\ALTIUM_TOOL\PCB_FOOTPRINTS\Altium_Footprint_Lib.PcbLib; Height: 0.45MM; Library Path: Y:\MIS_DATABASE\Library\ALTIUM_TOOL\SCHEMATICS_PARTS\MS_DISCRETE_Library.schlib; Mfr_name: TEXAS INSTRUMENTS; Mistral Part No: 130014110022-R; Package: X1SON2; Part_type: DIODE; Project: GALILEO_EVM; RoHS: RoHS; Temperature: -40°C+125°C; Tolerance: NA; Voltage: NA; Wattage: NA; Weight: 1mg; Datasheet: Y:\MIS_DATABASE\DATASHEETS\ICS\INTERFACE\TPD1E10B06-SER.PDF
Q9 Q10 Q17 = MOSFET_IRLML6401TR: TRANSISTOR MOSFET P-CHANNEL SOT23-3; Chkd/date: SHREESHAIL/020206; Crtd /date: MAZHAR/040505; Custom_Duty: 15%; Customs_HS_Code: 85412900; Distributor_name: DIGIKEY; Distributor_part_number: IRLML6401PBFCT-ND; Height: 1.11MM; Mfr_name: IRF; Mfr_part_number: IRLML6401TRPBF; Mistral Part No: 130009031213-P; Package: SOT23-3; Part_type: TRANSISTOR\MOSFET; Project: G4_SVGA; RoHS: Pb-Free; Temperature: -55°C+150°C; Tolerance: NA; Voltage: NA; Wattage: NA; Weight: NA; Datasheet: Y:\MIS_DATABASE\DATASHEETS\DISCRETES\TRANSISTORS_FETS\IRLML6401.PDF
R259 R283 R285 = RESISTOR: RES 10K 1/16W 1% 0402; Chkd/date: VASANTHA/201216; Crtd /date: GEETHA/290506; Custom_Duty: 15%; Customs_HS_Code: 85332119; Distributor_name: DIGIKEY; Distributor_part_number: 311-10.0KLRTR-ND; Footprint Path: Y:\MIS_DATABASE\Library\ALTIUM_TOOL\PCB_FOOTPRINTS\Altium_Footprint_Lib.PcbLib; Height: 0.40MM; Library Path: Y:\MIS_DATABASE\Library\ALTIUM_TOOL\SCHEMATICS_PARTS\MS_DISCRETE_Library.schlib; Mfr_name: YAGEO AMERICA; Mfr_part_number: RC0402FR-0710KL; Mistral Part No: 110015090015-R; Package: 0402; Part_type: RESISTORS\FIXED; Project: VOCERA; RoHS: RoHS; Temperature: -55°C+155°C; Tolerance: 1%; Voltage: NA; Wattage: 1/16W; Weight: 0.65mg; Datasheet: Y:\MIS_DATABASE\DATASHEETS\RESISTORS\RCXXXXL-SER_MAR18.PDF
R260 = RESISTOR: RES 21K 1/16W 1% 0402; Chkd/date: MANIRAJA/200319; Crtd /date: MANIRAJA/200319; Custom_Duty: 15%; Customs_HS_Code: 85332119; Distributor_name: DIGIKEY; Distributor_part_number: 311-21.0KLRCT-ND; Footprint Path: Y:\MIS_DATABASE\Library\ALTIUM_TOOL\PCB_FOOTPRINTS\Altium_Footprint_Lib.PcbLib; Height: 0.40MM; Library Path: Y:\MIS_DATABASE\Library\ALTIUM_TOOL\SCHEMATICS_PARTS\MS_DISCRETE_Library.schlib; Mfr_name: YAGEO AMERICA; Mfr_part_number: RC0402FR-0721KL; Mistral Part No: 110015080019-R; Package: 0402; Part_type: RESISTORS\FIXED; Project: OCTASIC_3000; RoHS: RoHS; Temperature: -55°C+155°C; Tolerance: 1%; Voltage: NA; Wattage: 1/16W; Weight: 0.65mg; Datasheet: Y:\MIS_DATABASE\DATASHEETS\RESISTORS\RCXXXXL-SER_MAR18.PDF
R266 = RESISTOR: RES 220K 1/16W 1% 0402; Chkd/date: MANIRAJA/230817; Crtd /date: MANIRAJA/230817; Custom_Duty: 15%; Customs_HS_Code: 85332119; Distributor_name: DIGIKEY; Distributor_part_number: 541-220KLCT-ND; Footprint Path: Y:\MIS_DATABASE\Library\ALTIUM_TOOL\PCB_FOOTPRINTS\Altium_Footprint_Lib.PcbLib; Height: 0.40MM; Library Path: Y:\MIS_DATABASE\Library\ALTIUM_TOOL\SCHEMATICS_PARTS\MS_DISCRETE_Library.schlib; Mfr_name: VISHAY; Mfr_part_number: CRCW0402220KFKED; Mistral Part No: 110017080025-R; Package: 0402; Part_type: RESISTORS\FIXED; Project: TI_MAXIE_CPB; RoHS: RoHS; Temperature: -55°C+155°C; Tolerance: 1%; Voltage: NA; Wattage: 1/16W; Weight: 0.65mg; Datasheet: Y:\MIS_DATABASE\DATASHEETS\RESISTORS\CRCW0603.PDF
R282 = RESISTOR: RES 6.34K 1/16W 1% 0402; Chkd/date: VASANTHA/281216; Crtd /date: SHREESHAIL/310707; Custom_Duty: 15%; Customs_HS_Code: 85332119; Distributor_name: DIGIKEY; Distributor_part_number: RT0402FRE076K34L-ND; Footprint Path: Y:\MIS_DATABASE\Library\ALTIUM_TOOL\PCB_FOOTPRINTS\Altium_Footprint_Lib.PcbLib; Height: 0.35MM; Library Path: Y:\MIS_DATABASE\Library\ALTIUM_TOOL\SCHEMATICS_PARTS\MS_DISCRETE_Library.schlib; Mfr_name: YAGEO AMERICA; Mfr_part_number: RT0402FRE076K34; Mistral Part No: 110009031024-R; Package: 0402; Part_type: RESISTORS\FIXED; Project: V8TS; RoHS: RoHS; Temperature: -55°C+155°C; Tolerance: 1%; Voltage: NA; Wattage: 1/16W; Weight: 0.65mg; Datasheet: Y:\MIS_DATABASE\DATASHEETS\RESISTORS\YAGEO_RT-SERIES.PDF
R284 = RESISTOR: RES 4.3K 1/16W 1% 0402; Chkd/date: VASANTHA/140616; Crtd /date: VASANTHA/140616; Custom_Duty: 15%; Customs_HS_Code: 85332119; Distributor_name: DIGIKEY; Distributor_part_number: 311-4.30KLRCT-ND; Footprint Path: Y:\MIS_DATABASE\Library\ALTIUM_TOOL\PCB_FOOTPRINTS\Altium_Footprint_Lib.PcbLib; Height: 0.40MM; Library Path: Y:\MIS_DATABASE\Library\ALTIUM_TOOL\SCHEMATICS_PARTS\MS_DISCRETE_Library.schlib; Mfr_name: YAGEO AMERICA; Mfr_part_number: RC0402FR-074K3L; Mistral Part No: 110016060004-R; Package: 0402; Part_type: RESISTORS\FIXED; Project: TMDXCSKCC; RoHS: RoHS; Temperature: -55°C+155°C; Tolerance: 1%; Voltage: NA; Wattage: 1/16W; Weight: 0.65mg; Datasheet: Y:\MIS_DATABASE\DATASHEETS\RESISTORS\RCXXXXL-SER_MAR18.PDF
SW4 SW5 SW7 = SW4_SKHUPLE010: SWITCH TACTILE SPST ST SMD; Chkd/date: MANIRAJA/051017; Crtd /date: MANIRAJA/051017; Custom_Duty: 24%; Customs_HS_Code: 85369090; Distributor_name: MOUSER; Distributor_part_number: 688-SKHMQLE010; Height: 3.10MM; Mfr_name: ALPS; Mistral Part No: 130017100007-R; Package: SMD; Part_type: ELECTRO-MECHANICAL\SWITCH; Project: TI_MAXIE_CPB; RoHS: RoHS; Temperature: -30°C+85°C; Tolerance: NA; Voltage: NA; Wattage: NA; Weight: NA; Datasheet: Y:\MIS_DATABASE\DATASHEETS\MISC\SWITCHES\SKHMQLE010.PDF
TP32 = TESTPOINT: TESTPOINT CIR 20 SMD; Chkd/date: SHREESHAIL/171006; Crtd /date: MAZHAR/171006; Custom_Duty: NA; Customs_HS_Code: NA; Distributor_name: NA; Distributor_part_number: NA; Footprint Path: Y:\MIS_DATABASE\Library\ALTIUM_TOOL\PCB_FOOTPRINTS\Altium_Footprint_Lib.PcbLib; Height: NA; Library Path: Y:\MIS_DATABASE\Library\ALTIUM_TOOL\SCHEMATICS_PARTS\MS_DISCRETE_Library.schlib; MECHANICAL 3D STEP FILE: NA; Mfr_name: LOCAL; Mistral Part No: NA; Package: SMD; Project: BT MODULE_CSRBC04; RoHS: NA; Temperature: NA; Tolerance: NA; Voltage: NA; Wattage: NA; Weight: NA; Datasheet: NA
U41 = SN74LVC1G11DCKR_SC70-6: IC SINGLE 3-INPUT POSITIVE-AND GATE SC70-6; Chkd/date: SHREESHAIL/220506; Crtd /date: MAZHAR/150506; Custom_Duty: 15%; Customs_HS_Code: 85423100; Distributor_name: DIGIKEY; Distributor_part_number: 296-18066-1-ND; Height: 1.10MM; Mfr_name: TEXAS INSTRUMENTS; Mistral Part No: 141009030230-R; Part_type: ICS\DIGITAL\GATES; Project: VOCERA; RoHS: Sb/ Br FREE; Datasheet: Y:\MIS_DATABASE\DATASHEETS\ICS\DIGITAL\GATES\SN74LVC1G.PDF
U50 = SN74LVC3G17DCUR_VSSOP8: IC TRIPLE SCHMITT-TRIGGER BUFFER VSSOP8; Chkd/date: MANIRAJA/280917; Crtd /date: MANIRAJA/280917; Custom_Duty: 15%; Customs_HS_Code: 85423100; Distributor_name: DIGIKEY; Distributor_part_number: 296-18818-1-ND; Height: 0.90MM; Mfr_name: TEXAS INSTRUMENTS; Mistral Part No: 141017090019-R; Package: VSSOP8; Part_type: ICS\DIGITAL\COMBINATIONAL; Project: TI_MAXIE_CPB; RoHS: RoHS; Temperature: -40°C+125°C; Tolerance: NA; Voltage: NA; Wattage: NA; Weight: 9.6mg; Datasheet: Y:\MIS_DATABASE\DATASHEETS\ICS\DIGITAL\COMBINATIONAL\SN74LVC3G17.PDF
U57 = SN74LVC1G17DCKR_SC70-5: IC SINGLE SCHMITT-TRIGGER BUFFER SC70-5; Chkd/date: MAZHAR/011210; Crtd /date: BAVISH/251110; Custom_Duty: 15%; Customs_HS_Code: 85423100; Distributor_name: DIGIKEY; Distributor_part_number: 296-11934-1-ND; Height: 1.10MM; Mfr_name: TEXAS INSTRUMENTS; Mistral Part No: 141010110012-R; Part_type: ICS\DIGITAL\COMBINATIONAL; Project: ITS-PWR_CARD; RoHS: RoHS; Temperature: -40°C+85°C; Tolerance: NA; Voltage: NA; Wattage: NA; Weight: NA; Datasheet: Y:\MIS_DATABASE\DATASHEETS\ICS\DIGITAL\COMBINATIONAL\SN74LVC1G17DCK.PDF
U74 = TPS3711DDCR_SOT23-6: IC 36V VOLTAGE DETECTOR SOT23-6; Chkd/date: MANIRAJA/091017; Crtd /date: MANIRAJA/091017; Custom_Duty: 15%; Customs_HS_Code: 85423100; Distributor_name: DIGIKEY; Distributor_part_number: 296-43278-1-ND; Height: 1.10MM; Mfr_name: TEXAS INSTRUMENTS; Mistral Part No: 142017100008-R; Package: SOT23-6; Part_type: ICS\POWER\MANAGEMENT; Project: TI_MAXIE_CPB; RoHS: RoHS; Temperature: -40°C+125°C; Tolerance: NA; Voltage: NA; Wattage: NA; Weight: 30mg; Datasheet: Y:\MIS_DATABASE\DATASHEETS\ICS\POWER\TPS3711D.PDF
U76 = TPS3897ADRYR_SON6: IC 1-CH ADJ VOLTAGE MONITOR SON6; Chkd/date: MANIRAJA/091017; Crtd /date: MANIRAJA/091017; Custom_Duty: 15%; Customs_HS_Code: 85423100; Distributor_name: DIGIKEY; Distributor_part_number: 296-29810-1-ND; Height: 0.60MM; Mfr_name: TEXAS INSTRUMENTS; Mistral Part No: 142017100007-R; Package: SON6; Part_type: ICS\POWER\MANAGEMENT; Project: TI_MAXIE_CPB; RoHS: RoHS; Temperature: -40°C+125°C; Tolerance: NA; Voltage: NA; Wattage: NA; Weight: NA; Datasheet: Y:\MIS_DATABASE\DATASHEETS\ICS\POWER\TPS389X.PDF

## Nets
DGND: C57.2 C144.1 C145.1 C146.1 C151.1 C155.1 C156.1 C157.1 C162.1 C163.1 C164.1 C165.1 C168.2 C169.2 C171.1 C173.1 C178.1 C179.1 C182.1 C183.1 C188.1 C189.1 C194.1 C245.2 C271.1 C277.2 C283.1 C411.1 C456.1 C457.1 C461.1 C464.1 C465.1 C467.1 C468.1 C529.1 D8.1 D10.1 D11.1 J25.10 J25.12 J25.16 J25.20 J29.3 J33.16 J33.57 J33.61 J33.62 J33.63 J33.64 Q9.3(D) Q10.3(D) Q17.3(D) R148.1 R177.1 R183.2 R260.2 R283.2 R322.2 R409.1 R507.1 R630.1 R631.1 R636.2 R638.2 R643.1 SW4.3 SW4.4 SW4.5(GND) SW5.3 SW5.4 SW5.5(GND) SW7.3 SW7.4 SW7.5(GND) U37.8(GND1) U37.9(GND2) U37.17(PAD) U41.2(GND) U45.2(GND) U46.3(A2) U46.5(GND) U46.6(B2) U47.3(GND) U48.2(GND) U50.4(GND) U52.3(GND) U53.3(GND) U55.2(GND) U56.3(A2) U56.5(GND) U56.6(B2) U57.3(GND) U60.7(2A) U60.8(GND) U60.9(3A) U60.12(4A) U74.2(GND) U74.4(GND) U74.6(GND) U76.2(GND) U93.3(GND) U94.3(GND) U98.8(GND1) U98.9(GND2) U98.17(PAD) ; also on sheet 2 3 4 5 6 7 8 9 10 11 12 13 14 15 16 17 18 19 20 21 22 23 24 28 29 30 39 40
VCC3V3_PREREG: C179.2 C283.2 R259.1 U57.5(VCC) U76.6(VCC) ; also on sheet 15 17
VCC3V3_R: J33.1 R411.1
VCC3V3_XDS: C171.2 C178.2 C464.2 U55.7(VCCB) U56.8(VCCB) U98.16(VCCB) ; also on sheet 28
VCC_3V3_MIPI: C164.2 FB21.2 R447.1 R459.2 R460.1 R461.1 U48.3(VCCA)
VCC_3V3_SYS: C144.2 C145.2 C146.2 C151.2 C155.2 C156.2 C157.2 C162.2 C163.2 C165.2 C173.2 C182.2 C183.2 C188.2 C189.2 C194.2 C411.2 C456.2 C457.2 C461.2 FB21.1 J25.5 J29.1 R150.1 R184.2 R187.2 R188.2 R285.1 R411.2 R455.1 R458.1 R476.2 R477.1 R534.2 R537.2 R540.2 R634.1 R635.1 R637.2 R639.2 R640.1 R641.1 R642.1 U37.1(VCCA) U37.16(VCCB) U41.5(VCC) U45.3(VCCA) U45.7(VCCB) U46.1(VCCA) U46.8(VCCB) U47.5(VCC) U48.7(VCCB) U50.8(VCC) U52.5(VCC) U53.5(VCC) U55.3(VCCA) U56.1(VCCA) U60.16(VCC) U93.5(VCC) U94.5(VCC) U98.1(VCCA) ; also on sheet 2 5 6 7 8 10 11 12 13 14 15 16 17 18 19 20 21 23 24 29 30 39 40
VCC_5V0: C271.2 R266.1 U74.5(VDD) ; also on sheet 4 6 17 18 20
VDD_CORE: R284.1 ; also on sheet 3 4 14 15
VDDAR_SENSE: R282.2 R283.1 R284.2 U76.3(SENSE)
VDDR_CORE: R282.1 ; also on sheet 3 4
VIN_MON_PORz_3V3_PG: C57.1 R259.2 U41.3(B) U74.1(OUT) ; also on sheet 16 17
cTI_TCK: R195.1 U60.3(1B2)
Debounce_GPIO_SoC/MCU: C465.2 D8.2 Q17.2(S) R534.1 SW5.1 SW5.2 U50.3(2A)
Debounce_MCU_RESETz: U50.1(1A) ; also on sheet 12
Debounce_WARM_RST: C467.2 D11.2 Q10.2(S) R537.1 SW4.1 SW4.2 U50.6(3A)
GPIO1_43_INTn: R471.2 ; also on sheet 6
GPIO_SoC/MCU: R470.1 R471.1 U50.5(2Y)
JTAG_cTI_RTCK: J25.9 R491.1 R636.1 R637.1
JTAG_cTI_TCK: J25.11 R188.1 R190.1 U53.2(B) U93.2(B)
JTAG_DIR: R148.2 U37.2(1DIR) U37.3(2DIR)
JTAG_EMU0: J25.13 R455.2 U45.8(B1) U48.8(B1)
JTAG_EMU1: J25.14 R458.2 U45.1(B2) U48.1(B2)
JTAG_EMU_RSTn: J25.15 R150.2 R449.1 U41.6(C)
JTAG_MIPI_EMU0: J33.38 R461.2 U48.5(A1)
JTAG_MIPI_EMU1: J33.40 R460.2 U48.4(A2)
JTAG_MIPI_RTCK: J33.7 R492.1 R638.1 R639.1
JTAG_MIPI_TCK: J33.3 R187.1 R189.1 U52.2(B) U94.2(B)
JTAG_MUX_SEL: J29.2 U60.1(S)
JTAG_TCK: R640.2 U37.12(1B2) U60.4(1A)
JTAG_TDI: J25.3 R410.2 R642.2 U37.10(2B2)
JTAG_TDIS: J25.4 R177.2
JTAG_TDO: J25.7 R450.1 U46.7(B1)
JTAG_TMS: J25.1 R451.1 R641.2 U37.11(2B1)
JTAG_TRST#: C529.2 R448.1 R643.2 R685.2 U37.13(1B1)
MCU_GPIO0_6: R470.2 ; also on sheet 12
MCU_RESETz: R477.2 U50.7(1Y) ; also on sheet 12 18
MIPI_TCK: R194.1 U60.2(1B1)
MIPI_TDI_R: J33.5 R410.1
MIPI_TDO_R: J33.4 R450.2
MIPI_TMS_R: J33.2 R451.2
MIPI_TRC_CLK: J33.13 ; also on sheet 19
MIPI_TRC_CTL: J33.17 ; also on sheet 19
MIPI_TRC_DAT00: J33.19 ; also on sheet 19
MIPI_TRC_DAT01: J33.21 ; also on sheet 19
MIPI_TRC_DAT02: J33.23 ; also on sheet 19
MIPI_TRC_DAT03: J33.25 ; also on sheet 19
MIPI_TRC_DAT04: J33.27 ; also on sheet 19
MIPI_TRC_DAT05: J33.29 ; also on sheet 19
MIPI_TRC_DAT06: J33.31 ; also on sheet 19
MIPI_TRC_DAT07: J33.33 ; also on sheet 19
MIPI_TRC_DAT08: J33.35 ; also on sheet 19
MIPI_TRC_DAT09: J33.37 ; also on sheet 19
MIPI_TRC_DAT10: J33.39 ; also on sheet 19
MIPI_TRC_DAT11: J33.41 ; also on sheet 19
MIPI_TRC_DAT12: J33.43 ; also on sheet 19
MIPI_TRC_DAT13: J33.45 ; also on sheet 19
MIPI_TRC_DAT14: J33.47 ; also on sheet 19
MIPI_TRC_DAT15: J33.49 ; also on sheet 19
MIPI_TRC_DAT16: J33.51 ; also on sheet 19
MIPI_TRC_DAT17: J33.53 ; also on sheet 19
MIPI_TRC_DAT18: J33.55 ; also on sheet 19
MIPI_TRC_DAT19: J33.18 ; also on sheet 19
MIPI_TRC_DAT20: J33.20 ; also on sheet 19
MIPI_TRC_DAT21: J33.22 ; also on sheet 19
MIPI_TRC_DAT22: J33.24 ; also on sheet 19
MIPI_TRC_DAT23: J33.26 ; also on sheet 19
MIPI_TRST#_R: J33.8 R448.2
PORz: R171.2 TP32.1(TP) ; also on sheet 12
SEL_XDS: U45.6(OE) U47.4(Y) U56.4(~{OE}) U98.14(~{2OE}) U98.15(~{1OE})
SEL_XDS110_INV: J25.8 J33.58 R183.1 R184.1 U37.14(~{2OE}) U37.15(~{1OE}) U46.4(~{OE}) U47.2(A) U52.1(A) U53.1(A) U55.6(OE) U60.15(~{OE}) U93.1(A) U94.1(A)
SoC_EMU0: J39.1 R634.2 U23.D10(EMU0) U45.5(A1) U55.5(A1)
SoC_EMU1: J40.1 R635.2 U23.E10(EMU1) U45.4(A2) U55.4(A2)
SOC_POWER_MON_PORz: R285.2 U41.1(A) U76.4(SENSE_OUT)
SoC_TCK: R147.2 R506.2 U23.B11(TCK)
SoC_TDI: U23.C11(TDI) U37.7(2A2) U98.4(1A1)
SoC_TDO: R323.1 U46.2(A1) U56.2(A1)
SoC_TMS: U23.C12(TMS) U37.6(2A1) U98.6(2A1)
SoC_TRST#: R322.1 U23.D11(TRSTN) U37.4(1A1) U98.7(2A2)
SoC_WARM_RESETZ: R476.1 U50.2(3Y) ; also on sheet 12
SUPERVISOR_DEBOUNCE_RSTn: C468.2 D10.2 Q9.2(S) R540.1 SW7.1 SW7.2 U57.2(A)
SUPERVISOR_MR_RSTn: U57.4(Y) U76.1(ENABLE)
TEST_GPIO1: Q17.1(G) ; also on sheet 30
TEST_PORZn: Q9.1(G) ; also on sheet 30
TEST_WARMRESETn: Q10.1(G) ; also on sheet 30
XDS110_DIR: R507.2 U98.2(1DIR) U98.3(2DIR)
XDS110_EMU0: U55.8(B1) ; also on sheet 28
XDS110_EMU1: U55.1(B2) ; also on sheet 28
XDS110_TCK: U98.12(1B2) ; also on sheet 28
XDS110_TDI: U98.13(1B1) ; also on sheet 28
XDS110_TDO: U56.7(B1) ; also on sheet 28
XDS110_TMS: U98.11(2B1) ; also on sheet 28
XDS110_TRST#: U98.10(2B2) ; also on sheet 28
N16753626: J33.6 R449.2
N16753680: J33.15 R409.2
N16754334: J33.12 R447.2
N16756061: J25.2 R685.1
N16937764: R147.1 U37.5(1A2)
N16938293: R506.1 U98.5(1A2)
N18275385: R459.1 U48.6(OE)
N18276744: C169.1 R190.2
N18280417: R195.2 U53.4(Y)
N18280437: R491.2 U93.4(Y)
N18280477: R194.2 U52.4(Y)
N18280857: R492.2 U94.4(Y)
N18289350: C277.1 U76.5(CT)
N24826481: C245.1 R260.1 R266.2 U74.3(SENSE)
N25395961: R323.2 U23.A12(TDO)
N26454965: R171.1 U41.4(Y)
N28906258: J40.2 R631.2
N28906289: J39.2 R630.2
N29046424: C168.1 R189.2

Not connected (* = marked no-connect by the designer): J25 17* 18* 19*; J33 9* 10* 11* 14* 28* 30* 32* 34* 36* 42* 44* 46* 48* 50* 52* 54* 56* 59* 60*; U47 1(NC)*; U57 1(NC)*; U60 5(2B1)* 6(2B2)* 10(3B2)* 11(3B1)* 13(4B2)* 14(4B1)*

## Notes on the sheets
sheet 25
- SoC POR_RST
- DEBOUNCE CIRCUIT
- VDD < 11V asserts PORz
- SoC WARM_RST
- Off Page Connections
- To Processor
- VOLTAGE SUPERVISOR
- Core Voltage Monitor (VDDAR_CORE/VDD_CORE)
- 5V OUTPUT MONITOR (VCC_5V0)
- R2
- R1
- To Processor
- delay > 10 ms by default
- For 0.75: VDD_CORE < 0.715 assert PORz
  For 0.80: VDD_CORE < 0.765 asserts PORz
  For 0.85: VDD_CORE < 0.82 asserts PORz
- CORE VOLTAGE
- RES TO BE PLACED
- 40us delay by default
- 0.75V
- R1 = 4.3K
- VDD < 4.6 asserts PORz
- 0.80V
- R2 = 5.23K
- 0.85V
- R2 = 6.34K
sheet 26
- MIPI 60 PIN CONNECTOR
- JTAG 20 PIN cTI CONNECTOR
- JTAG CLOCK BUFFER
- Off Page Connections
- From JTAG Buffer
- From SoC GPMC
- It should be connected to PORz of the SoC TBD
sheet 27
- JTAG BUFFER
- JTAG SoC SECTION
- BUFFER 20 PIN JTAG
- JTAG-DIR = H: A -> B
  JTAG_DIR = L: B -> A
  OE = H: output = Hi-Z
- BUFFER XDS110
- Placement of Buffers U37,U46,U56 and U98
  to be changed to reduce
  Stub length of the JTAG signals.
  These buffers need to be placed closer
  to the cTI-20pin connector -J25
- XDS110_DIR = H: A -> B
  XDS110_DIR = L: B -> A
  OE = H: output = Hi-Z
- Off Page Connections
- From XDS1100
  Debugger
